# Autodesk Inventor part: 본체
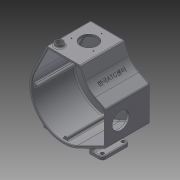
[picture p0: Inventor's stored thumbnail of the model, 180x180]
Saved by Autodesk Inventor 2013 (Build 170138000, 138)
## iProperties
Created: 2017-05
Part Number: 본체
Material: 일반
Document SubType Name: Modeling
Designer: mduedu
Density: 1 g/cm^3
Author: mduedu
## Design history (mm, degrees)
sketch "스케치1"
  geometry: L1 (-71.801, 35.28)-(-40, 100); L2 (-40, 100)-(40, 100); L3 (40, 100)-(59.768, 59.768); L4 (59.768, 59.768)-(100, 40); L5 (100, 40)-(100, -40); L6 (100, -40)-(35.28, -71.801); A1 r 80 centre (0, 0) between (-71.801, 35.28) and (35.28, -71.801); 3 further points
  constraints: 12 end point, 4 tangent, 2 midpoint, 2 point on circle, 1 centre point, 1 coincident, 1 horizontal, 1 horizontal alignment, 1 perpendicular, 1 vertical alignment
  dimensions: "d0" = 160 diameter of A1; "d2" = 100 distance from line of L2 point (0, 0); "d3" = 100 distance from line of L5 point (0, 0); "d4" = 80 distance of L1.end L2.end; "d5" = 80 distance of L4.end L5.end
extrude "돌출1" new body sketch "스케치1" distance "d6" = 5; taper "d7" = 0 deg
fillet "모깎기1" dims "d8" = 50
sketch "스케치2"
  geometry: C1 r 22 at (0, 0); 1 further point
  constraints: 1 centre point, 1 coincident
  dimensions: "d9" = 44 diameter of C1
extrude "돌출2" join sketch "스케치2" distance "d10" = 22.5; taper "d11" = 0 deg
sketch "스케치3"
  geometry: C1 r 18.5 at (0, 0); 1 further point
  constraints: 1 centre point, 1 coincident
  dimensions: "d12" = 37 diameter of C1
extrude "돌출3" cut sketch "스케치3" distance "d13" = 9; taper "d14" = 0 deg
fillet "모깎기2" dims "d15" = 3
sketch "스케치4"
  geometry: L1 (35.28, -71.801)-(100, -40) reference; L2 (100, -40)-(100, 40) reference; L3 (100, 40)-(75.073, 52.248) reference; L4 (52.248, 75.073)-(40, 100) reference; L5 (40, 100)-(-40, 100) reference; L6 (-40, 100)-(-71.801, 35.28) reference; L7 (-36.886, 95)-(36.886, 95); L8 (36.886, 95)-(47.76, 72.868); L9 (72.868, 47.76)-(95, 36.886); L10 (95, 36.886)-(95, -36.886); L11 (95, -36.886)-(33.075, -67.313); L12 (-67.313, 33.075)-(-36.886, 95); C1 r 25 at (0, 0) reference; A1 r 50 centre (97.123, 97.123) between (52.248, 75.073) and (75.073, 52.248) reference; A2 r 80 centre (0, 0) between (-71.801, 35.28) and (35.28, -71.801) reference; A3 r 55 centre (97.123, 97.123) between (47.76, 72.868) and (72.868, 47.76); A4 r 75 centre (0, 0) between (-67.313, 33.075) and (33.075, -67.313); 1 further point
  constraints: 12 end point, 4 point on circle, 2 centre point, 7 other
  dimensions: "d16" = 5 distance between parallel lines of L7 L5
extrude "돌출4" join sketch "스케치4" distance "d17" = 100; taper "d18" = 0 deg
sketch "스케치5"
  geometry: L1 (80, 0)-(0, 0) reference; C1 r 20 at (40, -45); 2 further points
  constraints: 1 centre point, 1 midpoint, 1 vertical alignment
  dimensions: "d19" = 40 diameter of C1; "d21" = 45 distance from line of C1.centre L1
extrude "돌출5" cut sketch "스케치5" stored distance "d22" = 100; taper "d23" = 0 deg
sketch "스케치6"
  geometry: L1 (0, 0)-(0, -105) reference; L2 (80, -105)-(0, -105) reference; C1 r 9 at (14, -89); 1 further point
  constraints: 1 centre point
  dimensions: "d24" = 18 diameter of C1; "d26" = 14 distance from line of C1.centre L1; "d27" = 16 distance from line of C1.centre L2
extrude "돌출6" join sketch "스케치6" distance "d28" = 7; taper "d29" = 0 deg
hole "구멍1" diameter "d32" = 14; stored, may be unused: countersink angle "d36" = 90 deg, drill point angle "d38" = 118 deg; dims "d33" = 6, "d34" = 4, "d35" = 2, "d37" = 8, "d39" = 10, "d40" = 10
sketch "스케치7"
  geometry: L1 (-105, 0)-(-105, 80) reference; L2 (0, 0)-(0, 80) reference; C1 r 20 at (-70, 40); 2 further points
  constraints: 1 centre point, 1 horizontal alignment, 1 midpoint
  dimensions: "d41" = 40 diameter of C1; "d42" = 35 distance from line of C1.centre L1
extrude "돌출7" cut sketch "스케치7" stored distance "d43" = 7; taper "d44" = 0 deg
node "작업 평면1"
sketch "스케치8"
  geometry: L1 (47.76, 72.868)-(36.886, 95) reference; L2 (36.886, 95)-(-36.886, 95) reference; L3 (-36.886, 95)-(-67.313, 33.075) reference; L4 (33.075, -67.313)-(95, -36.886) reference; L5 (95, -36.886)-(95, 36.886) reference; L6 (95, 36.886)-(72.868, 47.76) reference; L7 (95, 36.886)-(95, -36.886) reference; L8 (-36.886, 95)-(36.886, 95) reference; L9 (36.886, 95)-(47.76, 72.868) reference; L10 (-71, 4)-(-74.893, 4); L11 (-71, -4)-(-74.893, -4); L12 (-4, -71)-(-4, -74.893); L13 (4, -71)-(4, -74.893); L14 (30.394, 91)-(30.394, 95); L15 (34.394, 87)-(40.817, 87); L16 (30.394, 95)-(36.886, 95); L17 (36.886, 95)-(37.984, 92.764); L18 (91, 30.394)-(95, 30.394); L19 (87, 34.394)-(87, 40.817); L20 (87, 40.817)-(95, 36.886); L21 (95, 36.886)-(95, 30.394); C1 r 25 at (0, 0) reference; A1 r 75 centre (0, 0) between (-67.313, 33.075) and (33.075, -67.313) reference; A2 r 55 centre (97.123, 97.123) between (47.76, 72.868) and (72.868, 47.76) reference; A3 r 4 centre (-71, 0) between (-71, 4) and (-71, -4); A4 r 4 centre (0, -71) between (-4, -71) and (4, -71); A5 r 4 centre (34.394, 91) between (30.394, 91) and (34.394, 87); A6 r 75 centre (0, 0) between (-67.313, 33.075) and (33.075, -67.313) reference; A7 r 4 centre (91, 34.394) between (91, 30.394) and (87, 34.394); 1 further point
  constraints: 24 end point, 17 point on circle, 14 tangent, 5 point on line, 4 centre point, 3 equal radius, 3 perpendicular, 3 vertical, 2 collinear, 2 horizontal, 1 horizontal alignment, 1 parallel, 1 vertical alignment
  dimensions: "d46" = 8 diameter of A3
extrude "돌출8" join sketch "스케치8" stored distance "d49" = 7; taper "d50" = 0 deg
node "작업 평면2"
sketch "스케치9"
  geometry: L1 (71.801, 0)-(71.801, 105) reference; L2 (71.801, 0)-(-35.28, 0) reference; L3 (-35.28, 0)-(-35.28, 105) reference; L4 (71.801, 105)-(-35.28, 105) reference; L5 (40, 0)-(40, 105) reference; L6 (71.801, 52.5)-(-35.28, 52.5); L7 (71.801, 20)-(40, 20); L8 (40, 20)-(40, 85); L9 (40, 85)-(71.801, 85); L10 (71.801, 85)-(71.801, 20); 1 further point
  constraints: 10 end point, 2 midpoint, 2 parallel, 2 point on line, 1 horizontal, 1 perpendicular, 1 other
  dimensions: "d52" = 20 distance between parallel lines of L7 L2
extrude "돌출9" join sketch "스케치9" distance "d53" = 8; taper "d54" = 0 deg
fillet "모깎기3" dims "d55" = 8
sketch "스케치10"
  geometry: C1 r 4 at (-63.801, -28); C2 r 4 at (-63.801, -77); A1 r 8 centre (-63.801, -28) between (-63.801, -20) and (-71.801, -28) reference; A2 r 8 centre (-63.801, -77) between (-71.801, -77) and (-63.801, -85) reference; 1 further point
  constraints: 2 centre point, 2 coincident, 1 equal radius
  dimensions: "d56" = 8 diameter of C1
extrude "돌출10" cut sketch "스케치10" stored distance "d57" = 50.5; taper "d58" = 0 deg
sketch "스케치11"
  geometry: L1 (-63.801, -20)-(-40, -20) reference; L2 (-40, -20)-(-40, -85) reference; L3 (-40, -85)-(-63.801, -85) reference; L4 (-71.801, -77)-(-71.801, -28) reference; L5 (71.801, -77)-(71.801, -28) reference; L6 (40, -85)-(63.801, -85) reference; L7 (40, -20)-(40, -85) reference; L8 (63.801, -20)-(40, -20) reference; L9 (-40, -85)-(-48, -85); L10 (-48, -85)-(-48, -20); L11 (-48, -20)-(-40, -20); L12 (-40, -20)-(-40, -85); L13 (40, -85)-(48, -85); L14 (48, -85)-(48, -20); L15 (48, -20)-(40, -20); L16 (40, -20)-(40, -85); C1 r 4 at (-63.801, -28) reference; C2 r 4 at (-63.801, -77) reference; C3 r 4 at (63.801, -28) reference; C4 r 4 at (63.801, -77) reference; A1 r 8 centre (-63.801, -28) between (-63.801, -20) and (-71.801, -28) reference; A2 r 8 centre (-63.801, -77) between (-71.801, -77) and (-63.801, -85) reference; A3 r 8 centre (63.801, -28) between (71.801, -28) and (63.801, -20) reference; A4 r 8 centre (63.801, -77) between (63.801, -85) and (71.801, -77) reference; 1 further point
  constraints: 16 end point, 4 parallel, 2 horizontal, 2 perpendicular, 2 point on line
  dimensions: "d59" = 8 distance of L10.end L11.end; "d61" = 8 distance of L14.end L15.end
extrude "돌출11" join sketch "스케치11" stored distance "d62" = 5; taper "d63" = 0 deg
fillet "모깎기4" dims "d64" = 5
fillet "모깎기5" dims "d65" = 2
fillet "모깎기6" dims "d66" = 2
fillet "모깎기8" dims "d68" = 2
fillet "모깎기9" dims "d70" = 3, "d101" = 1
fillet "모깎기10" dims "d71" = 3
fillet "모깎기11" dims "d72" = 3
fillet "모깎기12" dims "d73" = 3
fillet "모깎기13" dims "d76" = 3
chamfer "모따기1" distance "d77" = 0.5; stored, may be unused: second distance "d78" = 2, angle "d79" = 45 deg
chamfer "모따기2" distance "d87" = 1; stored, may be unused: second distance "d88" = 2, angle "d89" = 45 deg
chamfer "모따기3" distance "d90" = 1; stored, may be unused: second distance "d91" = 2, angle "d92" = 45 deg
sketch "스케치14"
  geometry: 3 further points
  constraints: 3 other
hole "구멍2" sketch "스케치14" at (-55.375, -40), (-3.414, -40), (-29.394, -85) diameter "d93" = 2.459; stored, may be unused: countersink angle "d97" = 90 deg, drill point angle "d99" = 0 deg; dims "d94" = 6, "d95" = 4, "d96" = 2, "d98" = 8
sketch "스케치15"
  geometry: 3 further points
  constraints: 3 other
hole "구멍4" sketch "스케치15" at (-55.981, -14.394), (-4.019, -14.394), (-30, -59.394) diameter "d102" = 2.459; stored, may be unused: countersink angle "d106" = 90 deg, drill point angle "d108" = 0 deg; dims "d103" = 6, "d104" = 4, "d105" = 2, "d107" = 8
sketch "스케치16"
  geometry: 4 further points
  constraints: 4 other
hole "구멍6" sketch "스케치16" at (0, -71), (91, 34.394), (34.394, 91), (-71, 0) diameter "d109" = 2.459; stored, may be unused: countersink angle "d113" = 90 deg, drill point angle "d115" = 120 deg; dims "d110" = 8.5, "d111" = 4, "d112" = 2, "d114" = 10
node "작업 평면4"
sketch "스케치17"
  geometry: 2 further points
  constraints: 1 horizontal alignment, 1 other
  dimensions: "d116" = 52.5 distance of point (0, 16.14) point (52.5, 16.14)
feature "엠보싱2" sketch "스케치17" dims "d117" = 0.5, "d118" = 0
node "솔리드1"
mirror "대칭1"
node "투영된 루프1"
node "투영된 루프2"
node "투영된 루프3"
node "투영된 루프4"
node "투영된 루프5"
other parameters: "d45" = 95
